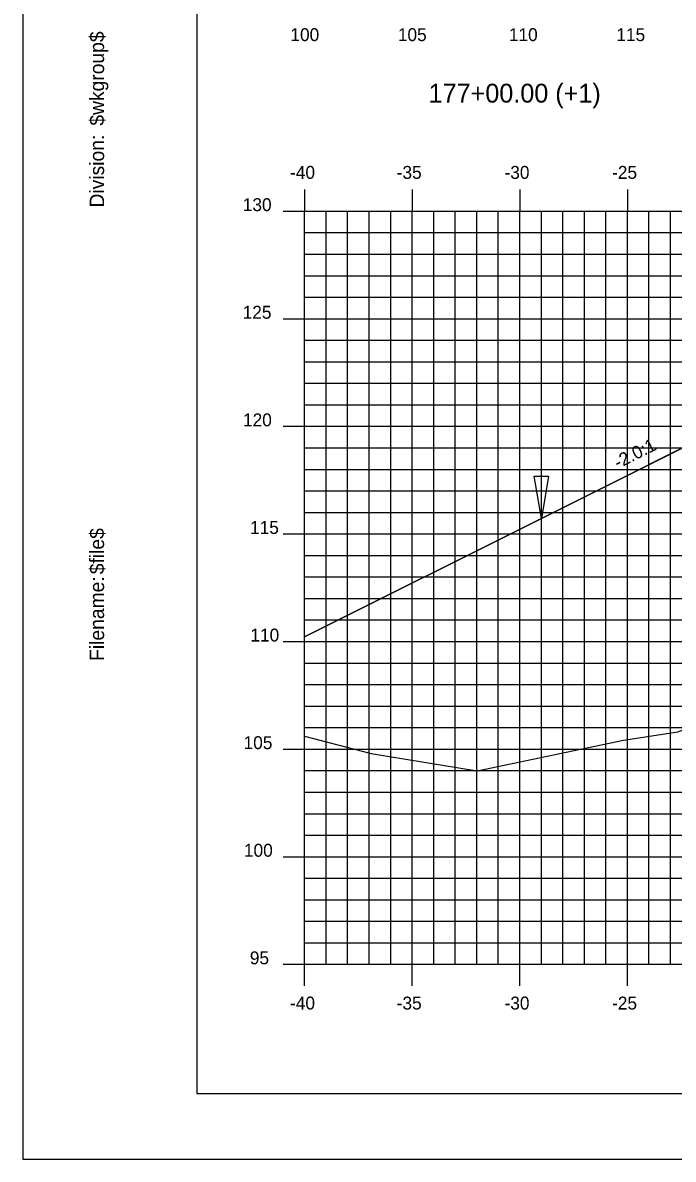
# Model space of a CAD drawing. Extents: x 850598 to 870284, y 366541 to 366651.
# Drawn here: x 858581 to 858611.3, y 366541.2 to 366594 of the extents above; entities that cross this region are included whole.
import ezdxf

# ---------------------------------------------------------------- set-up
doc = ezdxf.new("R2010")
doc.units = 0
for name, color, linetype in [('ANNOTATION', 7, 'Continuous'), ('BORDER', 7, 'Continuous'), ('D_Drainage_Ditch_Line', 7, 'Continuous'), ('D_Roadway_Centerline', 7, 'Continuous'), ('D_Roadway_SlopeLines', 7, 'Continuous'), ('H_V ANNOTATION', 7, 'Continuous'), ('MAJOR', 7, 'Continuous'), ('MINOR', 7, 'Continuous'), ('PLOT BOUNDARY', 7, 'Continuous'), ('S_Roadway_Centerline', 7, 'Continuous')]:
    doc.layers.add(name, color=color, linetype=linetype)

msp = doc.modelspace()

# ---------------------------------------------------------------- linework, layer by layer
at = {"layer": 'BORDER'}
for p, q in [((858589.133, 366649.225), (858589.133, 366544.225)), ((858589.133, 366544.225), (858749.133, 366544.225))]:
    msp.add_line(p, q, dxfattribs=at)
at = {"layer": 'D_Drainage_Ditch_Line'}
msp.add_line((858605.133, 366572.255), (858605.133, 366578.498), dxfattribs=at)
msp.add_lwpolyline([(858604.804, 366572.911), (858605.461, 366572.911), (858605.133, 366570.942)], close=True, dxfattribs=at)
at = {"layer": 'D_Roadway_Centerline'}
msp.add_lwpolyline([(858594.133, 366565.442), (858605.133, 366570.942), (858611.388, 366574.07), (858615.133, 366575.942), (858617.133, 366576.062), (858623.133, 366576.422), (858634.133, 366576.752), (858645.133, 366576.422), (858649.133, 366576.182), (858651.133, 366576.062), (858657.133, 366574.062), (858709.625, 366563.225), (858728.825, 366559.261), (858734.133, 366558.166)], dxfattribs=at)
at = {"layer": 'D_Roadway_SlopeLines'}
for points in [[(858615.133, 366575.942), (858605.133, 366570.942)], [(858605.133, 366570.942), (858594.133, 366565.442)]]:
    msp.add_lwpolyline(points, dxfattribs=at)
at = {"layer": 'MAJOR'}
for p, q in [((858594.133, 366586.227), (858594.133, 366585.225)), ((858594.133, 366586.227), (858594.133, 366585.225)), ((858599.133, 366586.227), (858599.133, 366585.225)), ((858599.133, 366586.227), (858599.133, 366585.225)), ((858604.133, 366586.227), (858604.133, 366585.225)), ((858604.133, 366586.227), (858604.133, 366585.225)), ((858609.133, 366586.227), (858609.133, 366585.225)), ((858609.133, 366586.227), (858609.133, 366585.225)), ((858593.131, 366585.225), (858594.133, 366585.225)), ((858593.131, 366585.225), (858594.133, 366585.225)), ((858594.133, 366585.225), (858734.133, 366585.225)), ((858594.133, 366550.225), (858594.133, 366585.225)), ((858594.133, 366550.225), (858594.133, 366585.225)), ((858594.133, 366585.225), (858734.133, 366585.225)), ((858594.133, 366585.225), (858734.133, 366585.225)), ((858594.133, 366550.225), (858594.133, 366585.225)), ((858594.133, 366550.225), (858594.133, 366585.225)), ((858594.133, 366585.225), (858734.133, 366585.225)), ((858599.133, 366550.225), (858599.133, 366585.225)), ((858599.133, 366550.225), (858599.133, 366585.225)), ((858604.133, 366550.225), (858604.133, 366585.225)), ((858604.133, 366550.225), (858604.133, 366585.225)), ((858609.133, 366550.225), (858609.133, 366585.225)), ((858609.133, 366550.225), (858609.133, 366585.225)), ((858593.131, 366580.225), (858594.133, 366580.225)), ((858593.131, 366580.225), (858594.133, 366580.225)), ((858594.133, 366580.225), (858734.133, 366580.225)), ((858594.133, 366580.225), (858734.133, 366580.225)), ((858593.131, 366575.225), (858594.133, 366575.225)), ((858593.131, 366575.225), (858594.133, 366575.225)), ((858594.133, 366575.225), (858734.133, 366575.225)), ((858594.133, 366575.225), (858734.133, 366575.225)), ((858593.131, 366570.225), (858594.133, 366570.225)), ((858593.131, 366570.225), (858594.133, 366570.225)), ((858594.133, 366570.225), (858734.133, 366570.225)), ((858594.133, 366570.225), (858734.133, 366570.225)), ((858593.131, 366565.225), (858594.133, 366565.225)), ((858593.131, 366565.225), (858594.133, 366565.225)), ((858594.133, 366565.225), (858734.133, 366565.225)), ((858594.133, 366565.225), (858734.133, 366565.225)), ((858593.131, 366560.225), (858594.133, 366560.225)), ((858593.131, 366560.225), (858594.133, 366560.225)), ((858594.133, 366560.225), (858734.133, 366560.225)), ((858594.133, 366560.225), (858734.133, 366560.225)), ((858593.131, 366555.225), (858594.133, 366555.225)), ((858593.131, 366555.225), (858594.133, 366555.225)), ((858594.133, 366555.225), (858734.133, 366555.225)), ((858594.133, 366555.225), (858734.133, 366555.225)), ((858593.131, 366550.225), (858594.133, 366550.225)), ((858593.131, 366550.225), (858594.133, 366550.225)), ((858594.133, 366550.225), (858734.133, 366550.225)), ((858594.133, 366550.225), (858734.133, 366550.225)), ((858594.133, 366549.223), (858594.133, 366550.225)), ((858594.133, 366550.225), (858734.133, 366550.225)), ((858594.133, 366550.225), (858734.133, 366550.225)), ((858594.133, 366549.223), (858594.133, 366550.225)), ((858599.133, 366549.223), (858599.133, 366550.225)), ((858599.133, 366549.223), (858599.133, 366550.225)), ((858604.133, 366549.223), (858604.133, 366550.225)), ((858604.133, 366549.223), (858604.133, 366550.225)), ((858609.133, 366549.223), (858609.133, 366550.225)), ((858609.133, 366549.223), (858609.133, 366550.225))]:
    msp.add_line(p, q, dxfattribs=at)
at = {"layer": 'MINOR'}
for p, q in [((858595.133, 366550.225), (858595.133, 366585.225)), ((858595.133, 366550.225), (858595.133, 366585.225)), ((858596.133, 366550.225), (858596.133, 366585.225)), ((858596.133, 366550.225), (858596.133, 366585.225)), ((858597.133, 366550.225), (858597.133, 366585.225)), ((858597.133, 366550.225), (858597.133, 366585.225)), ((858598.133, 366550.225), (858598.133, 366585.225)), ((858598.133, 366550.225), (858598.133, 366585.225)), ((858600.133, 366550.225), (858600.133, 366585.225)), ((858600.133, 366550.225), (858600.133, 366585.225)), ((858601.133, 366550.225), (858601.133, 366585.225)), ((858601.133, 366550.225), (858601.133, 366585.225)), ((858602.133, 366550.225), (858602.133, 366585.225)), ((858602.133, 366550.225), (858602.133, 366585.225)), ((858603.133, 366550.225), (858603.133, 366585.225)), ((858603.133, 366550.225), (858603.133, 366585.225)), ((858605.133, 366550.225), (858605.133, 366585.225)), ((858605.133, 366550.225), (858605.133, 366585.225)), ((858606.133, 366550.225), (858606.133, 366585.225)), ((858606.133, 366550.225), (858606.133, 366585.225)), ((858607.133, 366550.225), (858607.133, 366585.225)), ((858607.133, 366550.225), (858607.133, 366585.225)), ((858608.133, 366550.225), (858608.133, 366585.225)), ((858608.133, 366550.225), (858608.133, 366585.225)), ((858610.133, 366550.225), (858610.133, 366585.225)), ((858610.133, 366550.225), (858610.133, 366585.225)), ((858611.133, 366550.225), (858611.133, 366585.225)), ((858611.133, 366550.225), (858611.133, 366585.225)), ((858594.133, 366584.225), (858734.133, 366584.225)), ((858594.133, 366584.225), (858595.135, 366584.225)), ((858594.133, 366584.225), (858734.133, 366584.225)), ((858594.133, 366584.225), (858595.135, 366584.225)), ((858594.133, 366583.225), (858734.133, 366583.225)), ((858594.133, 366583.225), (858595.135, 366583.225)), ((858594.133, 366583.225), (858734.133, 366583.225)), ((858594.133, 366583.225), (858595.135, 366583.225)), ((858594.133, 366582.225), (858734.133, 366582.225)), ((858594.133, 366582.225), (858595.135, 366582.225)), ((858594.133, 366582.225), (858734.133, 366582.225)), ((858594.133, 366582.225), (858595.135, 366582.225)), ((858594.133, 366581.225), (858734.133, 366581.225)), ((858594.133, 366581.225), (858595.135, 366581.225)), ((858594.133, 366581.225), (858734.133, 366581.225)), ((858594.133, 366581.225), (858595.135, 366581.225)), ((858594.133, 366579.225), (858734.133, 366579.225)), ((858594.133, 366579.225), (858595.135, 366579.225)), ((858594.133, 366579.225), (858734.133, 366579.225)), ((858594.133, 366579.225), (858595.135, 366579.225)), ((858594.133, 366578.225), (858734.133, 366578.225)), ((858594.133, 366578.225), (858595.135, 366578.225)), ((858594.133, 366578.225), (858734.133, 366578.225)), ((858594.133, 366578.225), (858595.135, 366578.225)), ((858594.133, 366577.225), (858734.133, 366577.225)), ((858594.133, 366577.225), (858595.135, 366577.225)), ((858594.133, 366577.225), (858734.133, 366577.225)), ((858594.133, 366577.225), (858595.135, 366577.225)), ((858594.133, 366576.225), (858734.133, 366576.225)), ((858594.133, 366576.225), (858595.135, 366576.225)), ((858594.133, 366576.225), (858734.133, 366576.225)), ((858594.133, 366576.225), (858595.135, 366576.225)), ((858594.133, 366574.225), (858734.133, 366574.225)), ((858594.133, 366574.225), (858595.135, 366574.225)), ((858594.133, 366574.225), (858734.133, 366574.225)), ((858594.133, 366574.225), (858595.135, 366574.225)), ((858594.133, 366573.225), (858734.133, 366573.225)), ((858594.133, 366573.225), (858595.135, 366573.225)), ((858594.133, 366573.225), (858734.133, 366573.225)), ((858594.133, 366573.225), (858595.135, 366573.225)), ((858594.133, 366572.225), (858734.133, 366572.225)), ((858594.133, 366572.225), (858595.135, 366572.225)), ((858594.133, 366572.225), (858734.133, 366572.225)), ((858594.133, 366572.225), (858595.135, 366572.225)), ((858594.133, 366571.225), (858734.133, 366571.225)), ((858594.133, 366571.225), (858595.135, 366571.225)), ((858594.133, 366571.225), (858734.133, 366571.225)), ((858594.133, 366571.225), (858595.135, 366571.225)), ((858594.133, 366569.225), (858734.133, 366569.225)), ((858594.133, 366569.225), (858595.135, 366569.225)), ((858594.133, 366569.225), (858734.133, 366569.225)), ((858594.133, 366569.225), (858595.135, 366569.225)), ((858594.133, 366568.225), (858734.133, 366568.225)), ((858594.133, 366568.225), (858595.135, 366568.225)), ((858594.133, 366568.225), (858734.133, 366568.225)), ((858594.133, 366568.225), (858595.135, 366568.225)), ((858594.133, 366567.225), (858734.133, 366567.225)), ((858594.133, 366567.225), (858595.135, 366567.225)), ((858594.133, 366567.225), (858734.133, 366567.225)), ((858594.133, 366567.225), (858595.135, 366567.225)), ((858594.133, 366566.225), (858734.133, 366566.225)), ((858594.133, 366566.225), (858595.135, 366566.225)), ((858594.133, 366566.225), (858734.133, 366566.225)), ((858594.133, 366566.225), (858595.135, 366566.225)), ((858594.133, 366564.225), (858734.133, 366564.225)), ((858594.133, 366564.225), (858595.135, 366564.225)), ((858594.133, 366564.225), (858734.133, 366564.225)), ((858594.133, 366564.225), (858595.135, 366564.225)), ((858594.133, 366563.225), (858734.133, 366563.225)), ((858594.133, 366563.225), (858595.135, 366563.225)), ((858594.133, 366563.225), (858734.133, 366563.225)), ((858594.133, 366563.225), (858595.135, 366563.225)), ((858594.133, 366562.225), (858734.133, 366562.225)), ((858594.133, 366562.225), (858595.135, 366562.225)), ((858594.133, 366562.225), (858734.133, 366562.225)), ((858594.133, 366562.225), (858595.135, 366562.225)), ((858594.133, 366561.225), (858734.133, 366561.225)), ((858594.133, 366561.225), (858595.135, 366561.225)), ((858594.133, 366561.225), (858734.133, 366561.225)), ((858594.133, 366561.225), (858595.135, 366561.225)), ((858594.133, 366559.225), (858734.133, 366559.225)), ((858594.133, 366559.225), (858595.135, 366559.225)), ((858594.133, 366559.225), (858734.133, 366559.225)), ((858594.133, 366559.225), (858595.135, 366559.225)), ((858594.133, 366558.225), (858734.133, 366558.225)), ((858594.133, 366558.225), (858595.135, 366558.225)), ((858594.133, 366558.225), (858734.133, 366558.225)), ((858594.133, 366558.225), (858595.135, 366558.225)), ((858594.133, 366557.225), (858734.133, 366557.225)), ((858594.133, 366557.225), (858595.135, 366557.225)), ((858594.133, 366557.225), (858734.133, 366557.225)), ((858594.133, 366557.225), (858595.135, 366557.225)), ((858594.133, 366556.225), (858734.133, 366556.225)), ((858594.133, 366556.225), (858595.135, 366556.225)), ((858594.133, 366556.225), (858734.133, 366556.225)), ((858594.133, 366556.225), (858595.135, 366556.225)), ((858594.133, 366554.225), (858734.133, 366554.225)), ((858594.133, 366554.225), (858595.135, 366554.225)), ((858594.133, 366554.225), (858734.133, 366554.225)), ((858594.133, 366554.225), (858595.135, 366554.225)), ((858594.133, 366553.225), (858734.133, 366553.225)), ((858594.133, 366553.225), (858595.135, 366553.225)), ((858594.133, 366553.225), (858734.133, 366553.225)), ((858594.133, 366553.225), (858595.135, 366553.225)), ((858594.133, 366552.225), (858734.133, 366552.225)), ((858594.133, 366552.225), (858595.135, 366552.225)), ((858594.133, 366552.225), (858734.133, 366552.225)), ((858594.133, 366552.225), (858595.135, 366552.225)), ((858594.133, 366551.225), (858734.133, 366551.225)), ((858594.133, 366551.225), (858595.135, 366551.225)), ((858594.133, 366551.225), (858734.133, 366551.225)), ((858594.133, 366551.225), (858595.135, 366551.225))]:
    msp.add_line(p, q, dxfattribs=at)
at = {"layer": 'PLOT BOUNDARY'}
msp.add_lwpolyline([(858581.039, 366541.166), (858751.039, 366541.166), (858751.039, 366651.166), (858581.039, 366651.166)], close=True, dxfattribs=at)
at = {"layer": 'S_Roadway_Centerline'}
msp.add_lwpolyline([(858594.133, 366560.834), (858597.225, 366560.029), (858602.15, 366559.209), (858608.953, 366560.635), (858611.479, 366561.034), (858619.019, 366563.9), (858619.309, 366564.126), (858619.813, 366564.616), (858629.211, 366571.891), (858631.521, 366573.34), (858637.313, 366575.102), (858638.325, 366575.284), (858639.743, 366575.736), (858642.139, 366575.786), (858643.801, 366575.831), (858649.876, 366575.755), (858654.654, 366575.751), (858660.846, 366575.508)], dxfattribs=at)

# ---------------------------------------------------------------- texts
at = {"layer": 'ANNOTATION'}
msp.add_text('-2.0:1', height=0.6, rotation=26.5651, dxfattribs=at).set_placement((858608.688, 366573.238))
at = {"layer": 'BORDER'}
for s, p in [('$wkgroup$', (858584.818, 366589.195)), ('Division:', (858584.818, 366585.391)), ('$file$', (858584.818, 366568.351)), ('Filename:', (858584.818, 366564.324))]:
    msp.add_text(s, height=0.6696, rotation=90, dxfattribs=at).set_placement(p)
at = {"layer": 'H_V ANNOTATION'}
for s, height, p in [('100', 0.6, (858593.474, 366593.125)), ('105', 0.6, (858598.466, 366593.125)), ('110', 0.6, (858603.624, 366593.125)), ('115', 0.6, (858608.616, 366593.125)), ('177+00.00 (+1)', 0.87498, (858599.892, 366590.268)), ('-40', 0.6, (858593.458, 366586.725)), ('-35', 0.6, (858598.413, 366586.725)), ('-30', 0.6, (858603.421, 366586.725)), ('-25', 0.6, (858608.418, 366586.725)), ('130', 0.6, (858591.262, 366585.225)), ('125', 0.6, (858591.257, 366580.225)), ('120', 0.6, (858591.273, 366575.225)), ('115', 0.6, (858591.6, 366570.225)), ('110', 0.6, (858591.616, 366565.225)), ('105', 0.6, (858591.3, 366560.225)), ('100', 0.6, (858591.316, 366555.225)), ('95', 0.6, (858591.589, 366550.225)), ('-40', 0.6, (858593.458, 366548.125)), ('-35', 0.6, (858598.413, 366548.125)), ('-30', 0.6, (858603.421, 366548.125)), ('-25', 0.6, (858608.418, 366548.125))]:
    msp.add_text(s, height=height, dxfattribs=at).set_placement(p)

doc.saveas('drawing.dxf')
